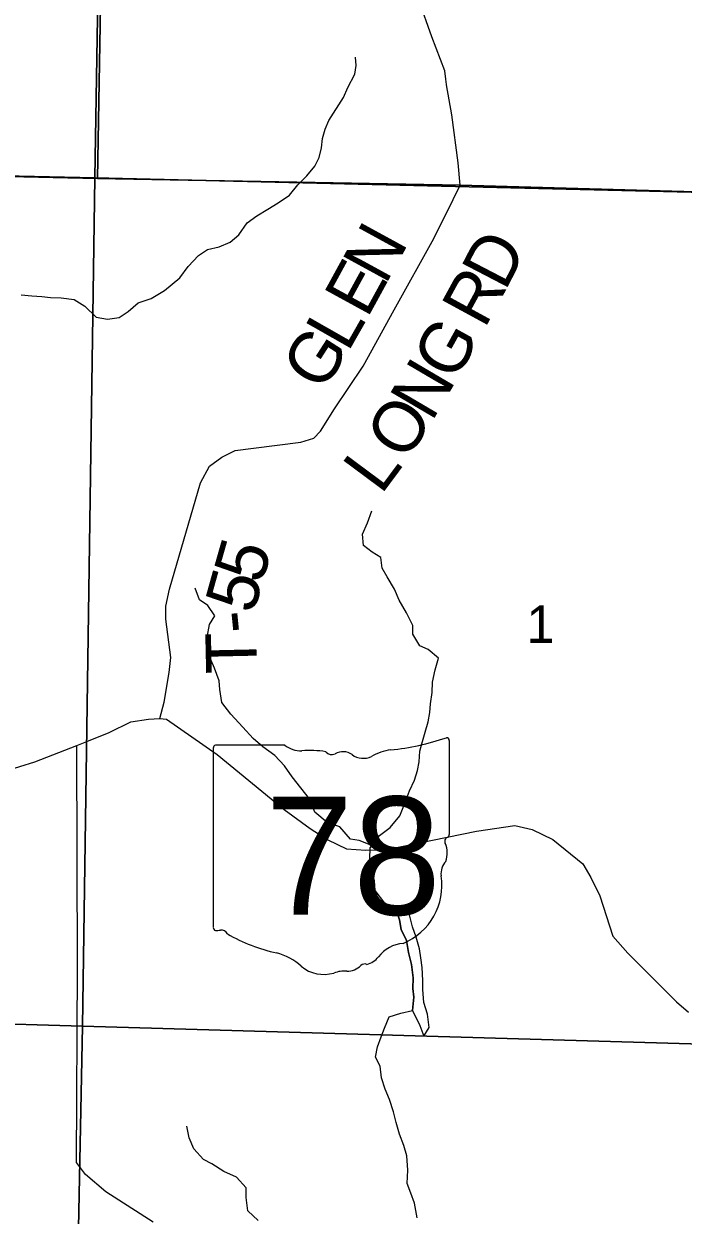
# Model space of a CAD drawing. Extents: x 2043100 to 2470832, y 443715 to 810583.
# Drawn here: x 2220493 to 2224382, y 633122 to 640149 of the extents above; entities that cross this region are included whole.
import ezdxf

# ---------------------------------------------------------------- set-up
doc = ezdxf.new("R2010")
doc.units = 0
for name, color, linetype in [('GM_X_County_Road', 7, 'Continuous'), ('GM_X_Minor_Lake', 7, 'Continuous'), ('GM_X_Minor_River', 7, 'Continuous'), ('GM_X_Section', 7, 'Continuous'), ('GM_X_Section_Text', 7, 'Continuous'), ('GM_X_State_Location', 7, 'Continuous'), ('GM_X_State_Route', 7, 'Continuous'), ('GM_X_State_Shield', 7, 'Continuous'), ('GM_X_Township', 7, 'Continuous'), ('GM_X_Township_Road', 7, 'Continuous'), ('GM_X_Township_Road_Text', 7, 'Continuous')]:
    doc.layers.add(name, color=color, linetype=linetype)

msp = doc.modelspace()

# ---------------------------------------------------------------- linework, layer by layer
at = {"layer": 'GM_X_County_Road'}
msp.add_lwpolyline([(2221255.4, 633080.7), (2220977.4, 633260.5), (2220856.6, 633362.1), (2220803.5, 633432.9), (2220810.1, 634580.8), (2220806.1, 635893)], dxfattribs=at)
at = {"layer": 'GM_X_Minor_Lake'}
for points in [[(2222692.4, 634916.1), (2222708.8, 634864.2), (2222719.3, 634806.3), (2222749.8, 634742.5), (2222762.5, 634670.5), (2222779.1, 634600.6), (2222789.8, 634522.7), (2222788.3, 634458.6), (2222792.8, 634408.6), (2222785.5, 634328.5)], [(2222785.5, 634328.5), (2222828.7, 634241.4), (2222853.2, 634177.6), (2222884.8, 634229.8), (2222874.2, 634307.8), (2222851.7, 634375.7), (2222847, 634453.7), (2222846.6, 634505.8), (2222842, 634581.8), (2222835.6, 634639.8), (2222827.2, 634693.7), (2222806.6, 634761.6), (2222786.2, 634823.5), (2222767.6, 634893.4), (2222692.4, 634916.1)]]:
    msp.add_lwpolyline(points, dxfattribs=at)
at = {"layer": 'GM_X_Minor_River'}
for points in [[(2221412.6, 638650.5), (2221462.3, 638718.1), (2221524.1, 638782.3), (2221576, 638818.5), (2221645.9, 638832.8), (2221709.8, 638861), (2221761.6, 638903.2), (2221811.4, 638975.5), (2221867.3, 639015.7), (2221933.1, 639055.9), (2221993, 639092.2), (2222060.8, 639138.5), (2222108.6, 639198.7), (2222162.4, 639252.9), (2222210.3, 639309.1), (2222236.1, 639361.2), (2222249.9, 639417.3), (2222255.7, 639471.4), (2222271.6, 639527.5), (2222291.4, 639577.6), (2222379, 639714), (2222404.8, 639774.1), (2222446.5, 639852.3), (2222454.4, 639902.4), (2222450.2, 639952.4)], [(2220478, 638549.5), (2220540.1, 638544), (2220600, 638540.6), (2220650, 638535), (2220714, 638533.5), (2220790.1, 638522.2), (2220852.3, 638482.7), (2220918.9, 638419.2), (2220986.9, 638405.8), (2221054.8, 638416.4), (2221108.4, 638452.9), (2221167.9, 638503.4), (2221243.7, 638528.1), (2221323.2, 638576.8), (2221412.6, 638650.5)], [(2222787.5, 636600.1), (2222750.8, 636673.8), (2222706.2, 636749.5), (2222679.7, 636813.3), (2222637, 636887), (2222606.6, 636938.8), (2222598.1, 637000.7), (2222547.8, 637032.3), (2222497.5, 637071.9), (2222490.9, 637137.9), (2222520.3, 637206.2), (2222545.7, 637276.5)], [(2222546, 635303.1), (2222470.9, 635332.5), (2222420.8, 635340), (2222356.2, 635411.5), (2222282.1, 635438.9), (2222209.6, 635498.3), (2222178.9, 635578.1), (2222126.4, 635641.7), (2222075.9, 635707.3), (2222031.3, 635773), (2221972.8, 635832.5), (2221902.4, 635884), (2221846, 635933.5), (2221785.5, 636001), (2221714.9, 636076.5), (2221660.3, 636146), (2221649.7, 636222), (2221645.2, 636274), (2221618.6, 636347.8), (2221592.1, 636407.7), (2221583.5, 636477.6), (2221575, 636531.6), (2221588.3, 636605.8), (2221619.9, 636656.1), (2221579.3, 636717.8), (2221529.1, 636751.3), (2221504.5, 636819.2)], [(2222814.2, 633105.9), (2222797.5, 633191.8), (2222775, 633251.7), (2222754.5, 633309.5), (2222757.8, 633387.6), (2222753, 633471.6), (2222734.5, 633533.5), (2222709.9, 633599.3), (2222689.3, 633669.2), (2222672.8, 633731.1), (2222650.2, 633805), (2222623.7, 633864.8), (2222603.1, 633932.7), (2222594.5, 634000.6), (2222568, 634054.4), (2222579.5, 634114.6), (2222601, 634174.8), (2222620.5, 634225), (2222647.9, 634291.3), (2222717.6, 634313.9), (2222785.5, 634328.5), (2222792.8, 634408.6), (2222788.3, 634458.6), (2222789.8, 634522.7), (2222779.1, 634600.6), (2222762.5, 634670.5), (2222749.8, 634742.5), (2222719.3, 634806.3), (2222708.8, 634864.2), (2222692.4, 634916.1), (2222622, 634961.5), (2222565.4, 635037.1), (2222560.9, 635093.1), (2222546.3, 635159), (2222533.8, 635222.9), (2222535.2, 635289), (2222590.5, 635361.5), (2222654.1, 635408.1), (2222711.4, 635476.7), (2222738.8, 635546.9), (2222768.1, 635625.2), (2222797.5, 635687.5), (2222815, 635745.7), (2222824.5, 635795.8), (2222830, 635857.9), (2222845.4, 635916.1), (2222860.9, 635970.3), (2222878.4, 636032.5), (2222887.9, 636086.6), (2222891.4, 636138.7), (2222900.9, 636204.8), (2222904.3, 636264.9), (2222919.7, 636339), (2222939, 636407.3), (2222878.6, 636458.8), (2222828.5, 636480.3), (2222787.9, 636548), (2222787.5, 636600.1)], [(2221875.1, 633089.8), (2221814.6, 633147.3), (2221803.9, 633225.3), (2221805.4, 633283.3), (2221746.9, 633346.9), (2221672.7, 633380.3), (2221602.3, 633425.7), (2221552.1, 633451.3), (2221495.6, 633512.8), (2221469.1, 633578.6), (2221454.5, 633646.6)]]:
    msp.add_lwpolyline(points, dxfattribs=at)
at = {"layer": 'GM_X_Section'}
for points in [[(2220999.9, 644558.9), (2220911.1, 639239.9), (2215649.9, 639357.3), (2215718.4, 644700.1)], [(2226283.1, 644449.8), (2226281.7, 644387.8), (2226228.4, 639113.1), (2220911.1, 639239.9), (2220999.9, 644558.9)], [(2215529.7, 639359.7), (2215649.9, 639357.3), (2220911.1, 639239.9), (2220838.7, 634236.9), (2215505, 634393.5)], [(2220911.1, 639239.9), (2226228.4, 639113.1), (2226188.3, 634080.6), (2220838.7, 634236.9)], [(2215505, 634393.5), (2220838.7, 634236.9), (2220732.4, 628875.8), (2215444.6, 629042.8)], [(2220838.7, 634236.9), (2226188.3, 634080.6), (2226179.6, 633768.3), (2226084.3, 628695.4), (2220732.4, 628875.8)]]:
    msp.add_lwpolyline(points, close=True, dxfattribs=at)
at = {"layer": 'GM_X_State_Route'}
msp.add_lwpolyline([(2220381.7, 635741), (2220558.7, 635794.9), (2220806.1, 635893), (2220874.1, 635920), (2220997.2, 635968.7), (2221123.9, 636031.6), (2221227.6, 636047.9), (2221295.5, 636051.4), (2221335.6, 636048.2), (2221634.5, 635838.4), (2222028, 635514.4), (2222182.6, 635403.6), (2222286.2, 635335.7), (2222397.4, 635282.1), (2222509.7, 635274.5), (2222633.7, 635279.2), (2223163.7, 635386.9), (2223389.1, 635419.9), (2223491.7, 635396.1), (2223613.1, 635338.6), (2223790.4, 635194.2), (2223838.2, 635113.1), (2223890.7, 635006.1), (2223968, 634767.4), (2224056.3, 634667.1), (2224342.8, 634380.9), (2224414.2, 634320.3)], dxfattribs=at)
at = {"layer": 'GM_X_State_Shield'}
for p, q in [((2221610.9, 635876.3), (2221610.9, 634819.7)), ((2222032.3, 635894.5), (2221624.6, 635894.5)), ((2223003.1, 635367.9), (2223003.1, 635920.7)), ((2223003, 635368.1), (2223003.1, 635367.9))]:
    msp.add_line(p, q, dxfattribs=at)
for centre, radius, start, end in [((2222507.2, 637335), 1476.4, 275.84447, 288.90645), ((2222987.7, 635923), 15.5, 351.86209, 97.738), ((2221626.9, 635878.6), 16.1, 98.1301, 188.1301), ((2222129.4, 636017.2), 156.4, 231.61951, 271.11188), ((2222181.3, 635301.3), 561.6, 80.48669, 94.98827), ((2222308.8, 635884), 45.1, 219.79206, 297.10237), ((2222375.1, 635761.9), 93.8, 54.46668, 119.14113), ((2222695.5, 635571.8), 297, 97.34618, 120.76885), ((2222496.2, 635929.4), 112.9, 233.85621, 294.82819), ((2222986.6, 635365.8), 16.6, 289.60381, 7.73413), ((2222999.5, 635327.4), 24, 107.94398, 210.33697), ((2222846.9, 635257.5), 144, 340.03296, 23.64957), ((2223058.6, 635136.6), 104.8, 136.8065, 186.92959), ((2222589.9, 635066.3), 369.3, 292.30889, 8.98584), ((2221627, 634817.4), 16.3, 171.95839, 258.30661), ((2221629.5, 634925.5), 124.2, 267.33899, 280.60386), ((2221654.9, 634758.7), 44.8, 29.74838, 93.27175), ((2222220.2, 635708.1), 1066.1, 240.41292, 257.1985), ((2221902.3, 634345), 333.6, 47.18416, 75.83597), ((2222745.6, 634523), 202.2, 94.40312, 142.57675), ((2222263.1, 634753.5), 211.7, 230.70037, 286.29184), ((2222400.9, 634674.3), 112.8, 268.77702, 315.54927), ((2222502.9, 634572), 31.8, 65.75173, 132.64842), ((2222489.4, 634717.3), 119.3, 282.87319, 323.27711), ((2222385.4, 634388.1), 173.9, 85.69512, 111.20995)]:
    msp.add_arc(centre, radius, start, end, dxfattribs=at)
at = {"layer": 'GM_X_Township'}
for points in [[(2221192, 660298.5), (2221175.2, 657998.8), (2221148.7, 653364.1), (2221047.8, 648017.8), (2221044, 645934.3), (2220986.4, 642634.5), (2220927.1, 639237.4), (2219619.4, 639265.9), (2216075, 639353.1), (2210326.8, 639537.9), (2204968.7, 639659.7), (2200443.3, 639770.7), (2194113.9, 639990), (2194110.3, 640430.4), (2194154.4, 645194.2), (2194418.6, 656109.1), (2194455.6, 656593), (2194569.9, 662033.3)], [(2232922, 639010.4), (2230294.1, 639053.5), (2227395.5, 639101), (2225149.7, 639137.8), (2223066.2, 639196.9), (2220927.1, 639237.4), (2220986.4, 642634.5), (2221044, 645934.3), (2221047.8, 648017.8), (2221148.7, 653364.1), (2221175.2, 657998.8), (2221192, 660298.5)], [(2209977.9, 623419.1), (2210251.5, 634590.7), (2210261.7, 635532.1), (2210323.9, 639312.1), (2210330.4, 639454.1), (2210326.8, 639537.9), (2216075, 639353.1), (2219619.4, 639265.9), (2220927.1, 639237.4), (2223066.2, 639196.9), (2225149.7, 639137.8), (2227395.5, 639101), (2230294.1, 639053.5), (2232922, 639010.4), (2234148.5, 638991.7), (2234148.8, 638924.2), (2234162.8, 635122.7), (2234171.5, 633589.1), (2234072.5, 630720.1)]]:
    msp.add_lwpolyline(points, dxfattribs=at)
at = {"layer": 'GM_X_Township_Road'}
for points in [[(2222986.2, 639788.9), (2222985.9, 639790.4), (2222982.2, 639821.7), (2222976.2, 639871.8), (2222900, 640071.9), (2222823.9, 640290), (2222777.8, 640378.1), (2222473.5, 640898.2), (2222451.5, 640936.2), (2222441.4, 641008.3), (2222427.3, 641210.5), (2222403.2, 641334.6), (2222337, 641536.7), (2222343, 641586.8), (2222358.9, 641622.9), (2222418.9, 641665), (2222530.8, 641697.2), (2222824.7, 641721.7), (2223240.6, 641722.3), (2223384.5, 641692.5), (2223460.5, 641682.6), (2223486.5, 641684.6), (2223528.5, 641712.7), (2223620.3, 641816.9)], [(2221295.5, 636051.4), (2221320.9, 636148.2), (2221350.1, 636322.6), (2221359.7, 636410.8), (2221330.7, 636637), (2221330.4, 636713.1), (2221351.9, 636813.4), (2221535.3, 637441.2), (2221588.9, 637539.6), (2221660.7, 637592), (2221740.5, 637632.5), (2221848.6, 637645), (2222126.6, 637680.4), (2222204.5, 637704.8), (2222242.3, 637747), (2222325.8, 637877.6), (2222494.8, 638128.8), (2222677.4, 638462.2), (2222912.4, 638883.5), (2223024.8, 639112.1), (2223066.2, 639196.9), (2223054.5, 639328.8), (2223018.4, 639611.2), (2222986.2, 639788.9)]]:
    msp.add_lwpolyline(points, dxfattribs=at)

# ---------------------------------------------------------------- texts
at = {"layer": 'GM_X_Section_Text'}
msp.add_text('1', height=220.8, rotation=0.00001, dxfattribs=at).set_placement((2223458.4, 636497.4))
at = {"layer": 'GM_X_State_Location'}
for s in ['s', 'r']:
    msp.add_text(s, height=0.0000833, dxfattribs=at).set_placement((2222291.5, 635278.2))
msp.add_text('78', height=0.0000833, rotation=0.00001, dxfattribs=at).set_placement((2222039.4, 635205))
at = {"layer": 'GM_X_State_Shield'}
msp.add_text('78', height=696.1, dxfattribs=at).set_placement((2221917.9, 634894.2))
at = {"layer": 'GM_X_Township_Road_Text'}
for s, rotation, p in [('N', 61.33482, (2222625.9, 638603.5)), ('D', 62.52465, (2223331.2, 638567)), ('E', 61.32347, (2222518.2, 638406.6)), ('R', 61.41765, (2223210.3, 638345)), ('L', 60.36226, (2222404.5, 638206.7)), ('G', 61.11161, (2223037.4, 638031.4)), ('G', 57.33546, (2222253.1, 637969.7)), ('N', 59.5429, (2222899.2, 637796)), ('O', 56.60582, (2222745, 637561.4)), ('L', 53.38466, (2222600.6, 637366.2)), ('5', 73.94379, (2221896.8, 636838.3)), ('5', 74.40485, (2221847.3, 636661)), ('-', 95.72349, (2221862.1, 636567.6)), ('T', 91.2858, (2221868.7, 636318.4))]:
    msp.add_text(s, height=300, rotation=rotation, dxfattribs=at).set_placement(p)

doc.saveas('drawing.dxf')
